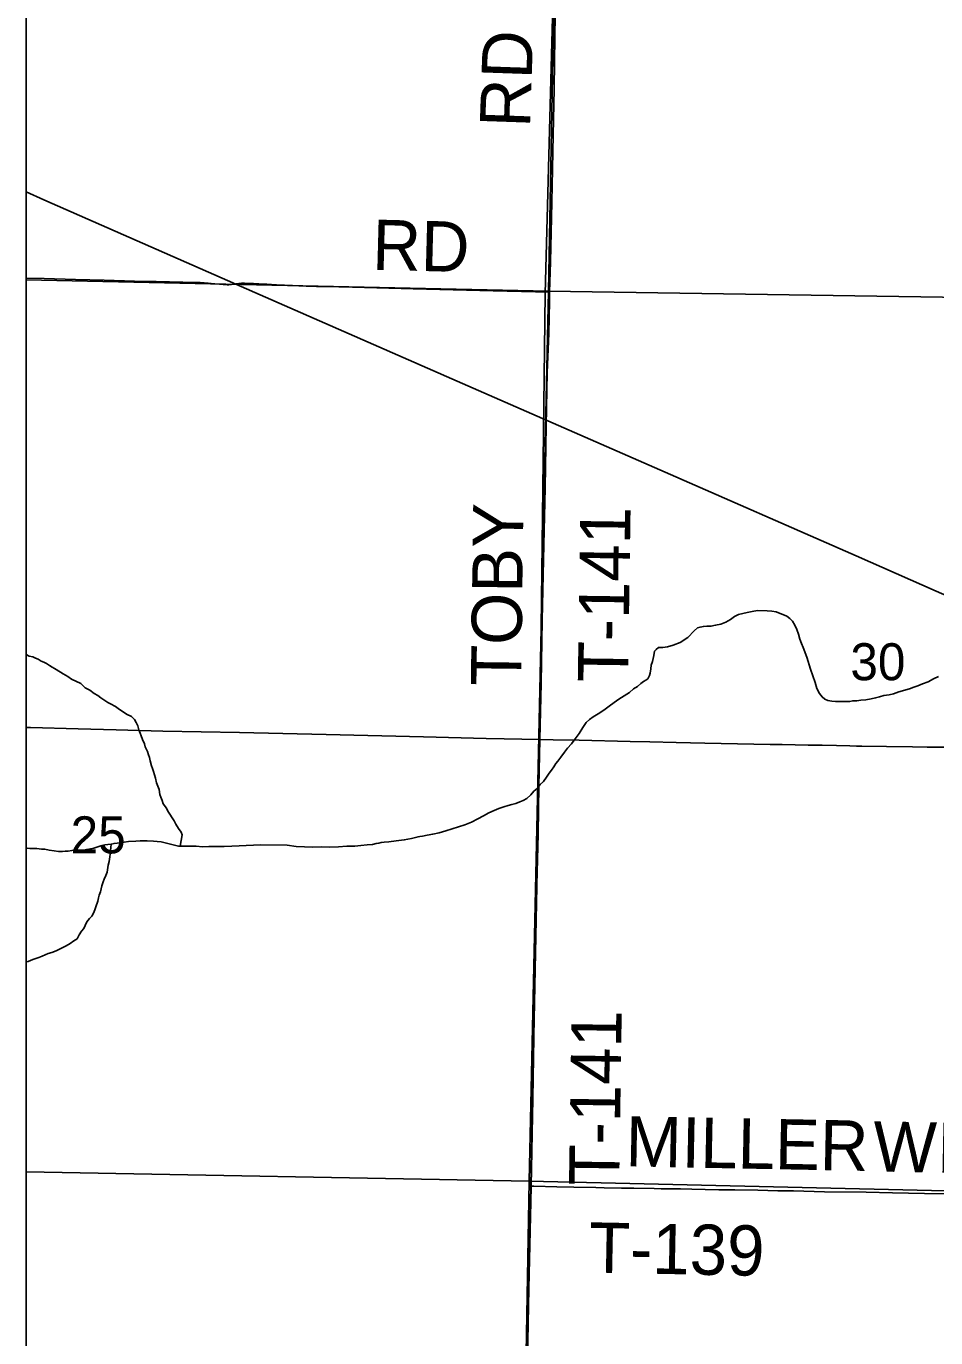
# Model space of a CAD drawing. Extents: x 0 to 34, y 0 to 22.
# Drawn here: x 23.9 to 24.414, y 18.82 to 19.562 of the extents above; entities that cross this region are included whole.
import ezdxf

# ---------------------------------------------------------------- set-up
doc = ezdxf.new("R2010")
doc.units = 0
for name, color, linetype in [('GM_X_Minor_River', 7, 'Continuous'), ('GM_X_Rail_Line', 7, 'Continuous'), ('GM_X_Section', 7, 'Continuous'), ('GM_X_Section_Text', 7, 'Continuous'), ('GM_X_Township_Road', 7, 'Continuous'), ('GM_X_Township_Road_Text', 7, 'Continuous'), ('GM_X_Unincorporated', 7, 'Continuous'), ('SC_Scratch1', 7, 'Continuous'), ('SH_Border', 7, 'Continuous'), ('SH_Cut_Line', 7, 'Continuous')]:
    doc.layers.add(name, color=color, linetype=linetype)

msp = doc.modelspace()

# ---------------------------------------------------------------- linework, layer by layer
at = {"layer": 'GM_X_Minor_River'}
for points in [[(24.41575, 19.19373), (24.41289, 19.19246), (24.40983, 19.19081), (24.40678, 19.18953), (24.40412, 19.18844), (24.40184, 19.18773), (24.39936, 19.18682), (24.39328, 19.18504), (24.39024, 19.18396), (24.38777, 19.18343), (24.38493, 19.18291), (24.38245, 19.1822), (24.38018, 19.18167), (24.37771, 19.18115), (24.37468, 19.18063), (24.37184, 19.18031), (24.36956, 19.17997), (24.3673, 19.18001), (24.36559, 19.17966), (24.36294, 19.1797), (24.36143, 19.17954), (24.35746, 19.17961), (24.35539, 19.17984), (24.35313, 19.18026), (24.35144, 19.18086), (24.34995, 19.18221), (24.34848, 19.18413), (24.34702, 19.187), (24.34595, 19.19043), (24.3447, 19.19406), (24.34345, 19.19787), (24.34132, 19.20473), (24.33915, 19.21007), (24.33825, 19.21236), (24.33736, 19.21484), (24.33665, 19.2177), (24.33557, 19.22037), (24.33449, 19.22285), (24.33321, 19.22496), (24.33172, 19.2265), (24.33005, 19.22786), (24.32405, 19.23024), (24.3216, 19.23066), (24.31896, 19.2309), (24.31348, 19.231), (24.31045, 19.23048), (24.3076, 19.22997), (24.30514, 19.22944), (24.30267, 19.22873), (24.30038, 19.22763), (24.29808, 19.22597), (24.29559, 19.22449), (24.29274, 19.22341), (24.2897, 19.2227), (24.28704, 19.22218), (24.28478, 19.22222), (24.28288, 19.22207), (24.28099, 19.22172), (24.27947, 19.22118)], [(24.27947, 19.22118), (24.27754, 19.21951), (24.27407, 19.21578), (24.26967, 19.21302), (24.26567, 19.21138), (24.26244, 19.21049), (24.25998, 19.21016), (24.25752, 19.2102), (24.25618, 19.20909), (24.25522, 19.20816), (24.25479, 19.2057), (24.25397, 19.2023), (24.25336, 19.20023), (24.25313, 19.19815), (24.25271, 19.19569), (24.2523, 19.19437), (24.25132, 19.1925), (24.25036, 19.19176), (24.24902, 19.19083), (24.24749, 19.18972), (24.24557, 19.18805), (24.24328, 19.18676), (24.24097, 19.18472), (24.2381, 19.18288), (24.23504, 19.18085), (24.23236, 19.179), (24.22948, 19.17697), (24.2266, 19.17474), (24.22335, 19.17271), (24.22048, 19.17087), (24.21838, 19.16939), (24.21664, 19.16772), (24.2147, 19.16491), (24.21256, 19.16154), (24.21042, 19.15854), (24.20829, 19.15574), (24.20597, 19.15331), (24.20422, 19.15088), (24.20228, 19.14807), (24.20054, 19.14583), (24.19938, 19.14452), (24.19821, 19.14265), (24.19704, 19.14078), (24.19568, 19.13909), (24.19413, 19.13685), (24.19238, 19.13442), (24.19046, 19.13274), (24.1889, 19.1305), (24.18698, 19.12883), (24.18524, 19.12677), (24.18293, 19.12473), (24.18102, 19.12363), (24.17912, 19.1229), (24.17683, 19.12199), (24.17455, 19.12128), (24.17246, 19.12074), (24.16999, 19.12003), (24.16714, 19.11913), (24.16447, 19.11804), (24.16161, 19.11658), (24.15856, 19.11493), (24.15531, 19.11328), (24.15169, 19.11145), (24.14788, 19.10981), (24.13723, 19.1064), (24.13343, 19.10533), (24.12983, 19.10463), (24.1266, 19.10393), (24.12394, 19.10341), (24.12243, 19.10325), (24.12148, 19.10308), (24.12015, 19.10272), (24.11787, 19.10219), (24.1137, 19.10132), (24.10916, 19.10083), (24.10499, 19.10015), (24.10234, 19.1), (24.10063, 19.09984), (24.09931, 19.09949), (24.09779, 19.09933), (24.0957, 19.09879), (24.09267, 19.09847), (24.08908, 19.09815), (24.08567, 19.09783), (24.08132, 19.09772), (24.07659, 19.09743), (24.07168, 19.09732), (24.06677, 19.09741), (24.06204, 19.09731), (24.05732, 19.09739), (24.0526, 19.09766), (24.04751, 19.09832), (24.03259, 19.09858), (24.02843, 19.09828), (24.02427, 19.09816), (24.0203, 19.09804), (24.01613, 19.09774), (24.01197, 19.09762), (24.00763, 19.09751), (24.00328, 19.09758), (23.99969, 19.09746)], [(23.98704, 19.09787), (23.98809, 19.10411), (23.98757, 19.10565), (23.98613, 19.10779), (23.9845, 19.11032), (23.98361, 19.11206), (23.98253, 19.11381), (23.98108, 19.11595), (23.98, 19.11751), (23.97929, 19.11924), (23.97748, 19.12177), (23.97679, 19.1237), (23.97608, 19.12544), (23.97556, 19.12697), (23.97509, 19.12984), (23.9737, 19.13369), (23.97302, 19.13619), (23.97201, 19.14003), (23.97131, 19.14176), (23.97079, 19.1433), (23.97012, 19.14599), (23.96961, 19.14791), (23.96909, 19.14945), (23.96859, 19.15136), (23.96715, 19.15389), (23.96683, 19.15561), (23.96578, 19.15812), (23.9649, 19.16024), (23.96438, 19.16178), (23.96368, 19.16351), (23.96299, 19.16582), (23.96211, 19.16775), (23.96122, 19.16949), (23.95956, 19.17107), (23.95676, 19.17249), (23.95527, 19.1733), (23.95267, 19.1751), (23.95045, 19.1767), (23.94766, 19.17831), (23.94617, 19.17912), (23.94208, 19.18173), (23.94041, 19.18293), (23.93836, 19.18414), (23.93596, 19.18593), (23.93335, 19.18735), (23.93077, 19.18972), (23.92554, 19.19218), (23.9235, 19.19377), (23.92089, 19.19518), (23.91941, 19.19619), (23.91606, 19.1982), (23.91457, 19.19901), (23.91308, 19.20001), (23.91141, 19.20102), (23.90992, 19.20183), (23.90842, 19.20245), (23.90675, 19.20346), (23.90525, 19.20408), (23.90376, 19.20489), (23.90169, 19.20534), (23.90001, 19.20615), (23.89999, 19.20616)], [(23.98609, 19.0977), (23.97621, 19.10032), (23.97393, 19.1004), (23.97185, 19.10066), (23.96844, 19.10077), (23.96655, 19.10084), (23.96446, 19.10072), (23.96199, 19.10061), (23.9578, 19.10037), (23.95533, 19.10007), (23.95323, 19.09976), (23.95132, 19.09944), (23.94961, 19.09931), (23.94808, 19.09898), (23.94618, 19.09867), (23.94446, 19.09853), (23.94294, 19.0982), (23.94102, 19.09751), (23.93814, 19.09665), (23.93642, 19.09633), (23.93413, 19.09583), (23.9326, 19.0955), (23.92805, 19.09566), (23.92577, 19.09535), (23.92367, 19.09504), (23.92196, 19.09491), (23.92044, 19.09477), (23.91816, 19.09485), (23.9157, 19.09512), (23.91287, 19.09559), (23.91042, 19.09606), (23.90853, 19.09612), (23.90607, 19.09639), (23.9038, 19.09647), (23.90209, 19.09652), (23.90058, 19.09657), (23.89999, 19.09652)], [(23.94808, 19.09898), (23.94752, 19.09329), (23.94728, 19.09178), (23.94681, 19.08913), (23.94636, 19.08706), (23.94566, 19.08308), (23.94503, 19.0812), (23.94402, 19.07915), (23.9434, 19.07764), (23.94275, 19.07538), (23.94188, 19.07199), (23.94125, 19.07011), (23.94082, 19.0686), (23.94038, 19.06671), (23.93933, 19.06351), (23.9387, 19.06182), (23.93807, 19.05994), (23.93707, 19.05826), (23.93569, 19.05679), (23.9343, 19.05493), (23.93329, 19.05287), (23.93247, 19.05119), (23.93129, 19.04971), (23.92989, 19.04766), (23.92887, 19.04541), (23.92694, 19.04434), (23.92479, 19.0427), (23.92248, 19.04144), (23.91997, 19.04019), (23.91688, 19.03859), (23.91439, 19.03772), (23.91247, 19.03702), (23.90901, 19.03562), (23.90708, 19.03492), (23.90535, 19.03422), (23.90363, 19.0337), (23.90113, 19.03265), (23.89999, 19.03231)], [(23.99969, 19.09746), (23.9961, 19.09771), (23.98704, 19.09787), (23.98609, 19.0977), (23.98609, 19.0977)]]:
    msp.add_lwpolyline(points, dxfattribs=at)
at = {"layer": 'GM_X_Rail_Line'}
msp.add_lwpolyline([(25.04289, 18.96722), (24.97136, 18.99851), (24.84106, 19.05549), (24.74766, 19.09615), (24.62543, 19.14978), (24.50887, 19.20089), (24.41444, 19.24202), (24.36928, 19.26197), (24.25818, 19.31069), (24.1436, 19.36084), (24.0185, 19.41563), (23.91, 19.46339), (23.89999, 19.46779)], dxfattribs=at)
at = {"layer": 'GM_X_Section'}
for points in [[(24.20471, 19.91929), (24.59058, 19.91145), (24.57889, 19.40577), (24.19525, 19.41166)], [(24.19525, 19.41166), (24.57889, 19.40577), (24.56605, 18.89955), (24.18438, 18.90842)], [(24.18438, 18.90842), (24.56605, 18.89955), (24.55748, 18.39165), (24.17542, 18.39998)]]:
    msp.add_lwpolyline(points, close=True, dxfattribs=at)
at = {"layer": 'GM_X_Township_Road'}
for points in [[(24.1904, 19.15814), (24.19114, 19.18996), (24.19175, 19.22559), (24.1927, 19.26813), (24.19331, 19.30047), (24.19393, 19.33558), (24.19451, 19.36566), (24.19537, 19.38773), (24.19582, 19.40594), (24.19585, 19.4112), (24.1963, 19.42827), (24.19688, 19.45326), (24.19729, 19.47126), (24.19791, 19.50016), (24.19844, 19.52601), (24.19873, 19.5415), (24.19902, 19.56838)], [(23.89999, 19.41895), (23.91019, 19.41876), (23.92778, 19.41835), (23.94402, 19.41794), (23.96112, 19.4174), (23.97349, 19.41708), (23.98857, 19.41683), (23.99536, 19.41662), (23.99836, 19.4165), (24.00061, 19.41638), (24.00275, 19.41621), (24.0046, 19.41605), (24.00658, 19.41588), (24.00925, 19.41564), (24.01138, 19.41547), (24.01266, 19.41539), (24.01356, 19.41535), (24.01459, 19.41535), (24.01599, 19.41547), (24.01726, 19.41564), (24.0187, 19.41584), (24.02026, 19.41605), (24.02178, 19.41613), (24.02335, 19.41613), (24.02606, 19.41605), (24.02844, 19.41597), (24.03157, 19.41584), (24.03609, 19.41559), (24.04155, 19.41531), (24.04591, 19.41506), (24.05043, 19.41481), (24.05401, 19.41469), (24.05828, 19.41457), (24.06416, 19.4144), (24.06901, 19.41428), (24.08446, 19.41395), (24.11874, 19.41305), (24.16399, 19.41186), (24.19585, 19.4112)], [(23.89999, 19.16495), (23.90236, 19.1649), (23.92936, 19.1642), (23.95086, 19.16366), (23.97716, 19.16288), (24.02055, 19.16206), (24.06963, 19.16092), (24.12459, 19.15959), (24.16, 19.15877), (24.1904, 19.15814)], [(24.17573, 18.39979), (24.1763, 18.44163), (24.17737, 18.49675), (24.17905, 18.57196), (24.18004, 18.62309), (24.18119, 18.68096), (24.18201, 18.73283), (24.18296, 18.7808), (24.18311, 18.79142), (24.18349, 18.81779), (24.18411, 18.84767), (24.18522, 18.89662), (24.18541, 18.90554), (24.18649, 18.95502), (24.18727, 19.0124), (24.18805, 19.05416), (24.18941, 19.10479), (24.18978, 19.13188), (24.1904, 19.15814)], [(24.1904, 19.15814), (24.19792, 19.15798), (24.21252, 19.15765), (24.2414, 19.15704), (24.25258, 19.15677), (24.26748, 19.15639), (24.28362, 19.15609), (24.32058, 19.15527), (24.32741, 19.15521), (24.34199, 19.15496), (24.35006, 19.15484), (24.35814, 19.15467), (24.36559, 19.15451), (24.36931, 19.15444), (24.37241, 19.15439), (24.38639, 19.1542), (24.40099, 19.15392), (24.40937, 19.15381), (24.4221, 19.15369)], [(24.18541, 18.90554), (24.18702, 18.90548), (24.19995, 18.90504), (24.20958, 18.90487), (24.222, 18.90466), (24.22666, 18.90459), (24.2366, 18.90446), (24.24344, 18.90437), (24.25493, 18.90417), (24.25897, 18.90407), (24.26176, 18.90402), (24.26984, 18.9039), (24.27636, 18.90379), (24.28381, 18.90366), (24.29158, 18.90352), (24.30059, 18.90337), (24.31364, 18.90316), (24.32482, 18.90294), (24.33383, 18.90283), (24.35122, 18.90239), (24.37483, 18.90204), (24.38974, 18.90173), (24.40776, 18.90139), (24.43354, 18.90089)]]:
    msp.add_lwpolyline(points, dxfattribs=at)
at = {"layer": 'GM_X_Unincorporated'}
for points in [[(23.89999, 19.92886), (23.89999, 19.41812), (24.19525, 19.41166), (24.20471, 19.91929)], [(23.89999, 19.41812), (23.89999, 18.91368), (24.18438, 18.90842), (24.19525, 19.41166)], [(23.89999, 18.91368), (23.89999, 18.40687), (24.17542, 18.39998), (24.18438, 18.90842)]]:
    msp.add_lwpolyline(points, close=True, dxfattribs=at)
at = {"layer": 'SC_Scratch1'}
msp.add_lwpolyline([(24.21209, 20.23613), (23.89999, 20.23613), (23.89999, 18.40604), (24.17532, 18.39981), (24.18524, 18.90616), (24.18987, 19.13136), (24.1904, 19.15849), (24.19341, 19.41028), (24.20131, 19.70851), (24.20462, 19.8336), (24.20479, 19.85918), (24.20479, 19.86099)], close=True, dxfattribs=at)
msp.add_lwpolyline([(27.11465, 20.23613), (24.21209, 20.23613), (24.20479, 19.86099), (24.20479, 19.85918), (24.20462, 19.8336), (24.20131, 19.70851), (24.19341, 19.41028), (24.1904, 19.15849), (24.18987, 19.13136), (24.18524, 18.90616), (24.17532, 18.39981), (24.16469, 17.88798), (24.16468, 17.88744), (24.15485, 17.3809)], dxfattribs=at)
at = {"layer": 'SH_Border'}
msp.add_lwpolyline([(23.89999, 20.23613), (23.89999, 13.43613), (30.69999, 13.43613), (30.69999, 20.23613)], close=True, dxfattribs=at)
at = {"layer": 'SH_Cut_Line'}
msp.add_lwpolyline([(30.09296, 20.23613), (23.89999, 20.23613), (23.89999, 13.43613)], dxfattribs=at)

# ---------------------------------------------------------------- texts
at = {"layer": 'GM_X_Section_Text'}
for s, p in [('30', (24.36592, 19.19164)), ('25', (23.92509, 19.09373))]:
    msp.add_text(s, height=0.020928, rotation=0.00001, dxfattribs=at).set_placement(p)
at = {"layer": 'GM_X_Township_Road_Text'}
for s, rotation, p in [('RD', 88.02522, (24.18476, 19.50387)), ('RD', 358.51748, (24.09537, 19.42382)), ('TOBY', 89.24276, (24.17974, 19.18822)), ('T-141', 89.15739, (24.24022, 19.19026)), ('T-141', 89.15739, (24.23522, 18.90568)), ('MILLER', 358.8918, (24.23864, 18.91674)), ('WILLIAMS', 358.90102, (24.37863, 18.91383)), ('T-139', 358.87624, (24.21787, 18.85669))]:
    msp.add_text(s, height=0.028409, rotation=rotation, dxfattribs=at).set_placement(p)

doc.saveas('drawing.dxf')
